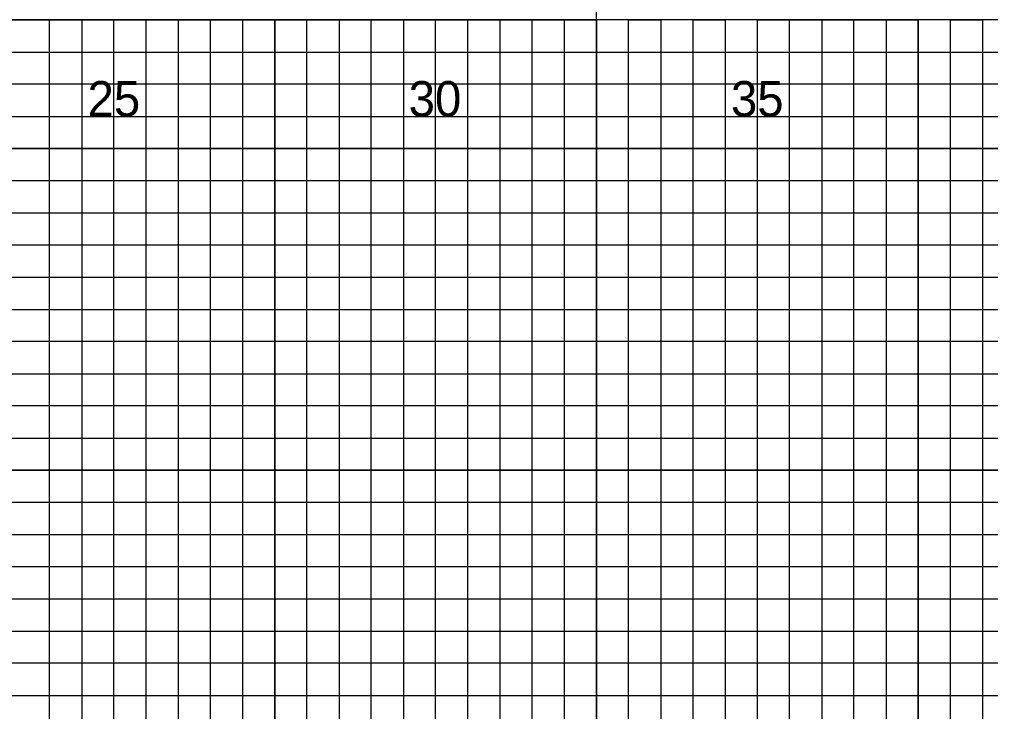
# Model space of a CAD drawing. Extents: x -4 to 103, y -2 to 6583.
# Drawn here: x 74.78 to 89.88, y 334.55 to 345.31 of the extents above; entities that cross this region are included whole.
import ezdxf

# ---------------------------------------------------------------- set-up
doc = ezdxf.new("R2010")
doc.units = 0
for name, color, linetype in [('Prop XS Offset Labels', 7, 'Continuous'), ('Sheet Cross Section CELL', 7, 'Continuous'), ('Sheet Cross Section Grid Major CELL', 7, 'Continuous'), ('Sheet Cross Section Grid Middle CELL', 7, 'Continuous'), ('Sheet DOT Grid CELL', 7, 'Continuous')]:
    doc.layers.add(name, color=color, linetype=linetype)

msp = doc.modelspace()

# ---------------------------------------------------------------- linework, layer by layer
at = {"layer": 'Sheet Cross Section CELL'}
for points in [[(83.75, 348.3), (74.25, 348.3), (74.25, 345.3), (83.75, 345.3)], [(83.75, 348.3), (90, 348.3), (90, 345.3), (83.75, 345.3)]]:
    msp.add_lwpolyline(points, close=True, dxfattribs=at)
at = {"layer": 'Sheet Cross Section Grid Major CELL'}
for points in [[(76.25, 283.3), (76.25, 345.3), (78.75, 345.3), (78.75, 283.3)], [(81.25, 283.3), (81.25, 345.3), (83.75, 345.3), (83.75, 283.3)], [(86.25, 283.3), (86.25, 345.3), (88.75, 345.3), (88.75, 283.3)], [(0, 340.8), (102.5, 340.8), (102.5, 343.3), (0, 343.3)], [(0, 335.8), (102.5, 335.8), (102.5, 338.3), (0, 338.3)]]:
    msp.add_lwpolyline(points, dxfattribs=at)
at = {"layer": 'Sheet Cross Section Grid Middle CELL'}
for points in [[(0, 344.8), (102.5, 344.8), (102.5, 345.3), (0, 345.3)], [(75.25, 283.3), (75.25, 345.3), (75.75, 345.3), (75.75, 283.3)], [(76.75, 283.3), (76.75, 345.3), (77.25, 345.3), (77.25, 283.3)], [(77.75, 283.3), (77.75, 345.3), (78.25, 345.3), (78.25, 283.3)], [(79.25, 283.3), (79.25, 345.3), (79.75, 345.3), (79.75, 283.3)], [(80.25, 283.3), (80.25, 345.3), (80.75, 345.3), (80.75, 283.3)], [(81.75, 283.3), (81.75, 345.3), (82.25, 345.3), (82.25, 283.3)], [(82.75, 283.3), (82.75, 345.3), (83.25, 345.3), (83.25, 283.3)], [(84.25, 283.3), (84.25, 345.3), (84.75, 345.3), (84.75, 283.3)], [(85.25, 283.3), (85.25, 345.3), (85.75, 345.3), (85.75, 283.3)], [(86.75, 283.3), (86.75, 345.3), (87.25, 345.3), (87.25, 283.3)], [(87.75, 283.3), (87.75, 345.3), (88.25, 345.3), (88.25, 283.3)], [(89.25, 283.3), (89.25, 345.3), (89.75, 345.3), (89.75, 283.3)], [(0, 343.8), (102.5, 343.8), (102.5, 344.3), (0, 344.3)], [(0, 342.3), (102.5, 342.3), (102.5, 342.8), (0, 342.8)], [(0, 341.3), (102.5, 341.3), (102.5, 341.8), (0, 341.8)], [(0, 339.8), (102.5, 339.8), (102.5, 340.3), (0, 340.3)], [(0, 338.8), (102.5, 338.8), (102.5, 339.3), (0, 339.3)], [(0, 337.3), (102.5, 337.3), (102.5, 337.8), (0, 337.8)], [(0, 336.3), (102.5, 336.3), (102.5, 336.8), (0, 336.8)], [(0, 334.8), (102.5, 334.8), (102.5, 335.3), (0, 335.3)]]:
    msp.add_lwpolyline(points, dxfattribs=at)
at = {"layer": 'Sheet DOT Grid CELL'}
for p, q in [((76.25, 283.3), (76.25, 345.3)), ((78.75, 283.3), (78.75, 345.3)), ((81.25, 283.3), (81.25, 345.3)), ((83.75, 283.3), (83.75, 345.3)), ((86.25, 283.3), (86.25, 345.3)), ((88.75, 283.3), (88.75, 345.3)), ((0, 343.3), (102.5, 343.3)), ((0, 340.8), (102.5, 340.8)), ((0, 338.3), (102.5, 338.3)), ((0, 335.8), (102.5, 335.8))]:
    msp.add_line(p, q, dxfattribs=at)

# ---------------------------------------------------------------- texts
at = {"layer": 'Prop XS Offset Labels'}
for s, p in [('25', (75.84, 343.8)), ('30', (80.831, 343.8)), ('35', (85.84, 343.8))]:
    msp.add_text(s, height=0.55, dxfattribs=at).set_placement(p)

doc.saveas('drawing.dxf')
